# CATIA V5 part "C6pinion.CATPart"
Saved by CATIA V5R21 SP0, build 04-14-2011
Part number: C6pinion
Bounding box of the stored display mesh (mm): x 0 to 31.75, y -12.556 to 12.556, z -12.696 to 12.696
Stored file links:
  C:\Users\User\Desktop\B.D.M.A\Chapter6\C6pinion.CATPart
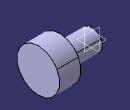
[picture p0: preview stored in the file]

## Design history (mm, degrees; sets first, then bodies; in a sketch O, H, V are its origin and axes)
Body1 (main body)
  Sketch1 on xy-plane, origin (0, 0, 0), H (1, 0, 0), V (0, 1, 0)
    line L1 (0, 0) -> (31.75, 0)
    line L2 (31.75, 0) -> (31.75, 12.7)
    line L3 (31.75, 12.7) -> (19.05, 12.7)
    line L4 (19.05, 12.7) -> (19.05, 6.35)
    line L5 (19.05, 6.35) -> (0, 6.35)
    point P5 (0, 6.35)
    line L6 (0, 6.35) -> (0, 0)
    length L6 = 6.35
    length L2 = 12.7
    length L3 = 12.7
    length L5 = 19.05
    horizontal: L1 H, L3 H, L5 H
    vertical: L2 V, L4 V, L6 V
    coincidence: P5 V
  Shaft1: profile Sketch1, axis Sketch1.L1, angle 360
